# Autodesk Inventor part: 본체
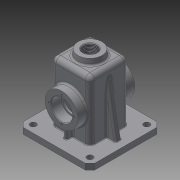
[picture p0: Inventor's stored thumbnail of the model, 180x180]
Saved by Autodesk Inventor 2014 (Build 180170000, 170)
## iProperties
Created: 2017-08
Part Number: 본체
Material: 일반
Document SubType Name: Modeling
Designer: user
Density: 1 g/cm^3
Appearance: 기본값
Author: user
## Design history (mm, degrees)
sketch "스케치1"
  geometry: L1 (32.5, -32.5)-(-32.5, -32.5); L2 (-32.5, -32.5)-(-32.5, 32.5); L3 (-32.5, 32.5)-(32.5, 32.5); L4 (32.5, 32.5)-(32.5, -32.5); L5 (32.5, -32.5)-(-32.5, 32.5); L6 (-32.5, -32.5)-(32.5, 32.5); 1 further point
  constraints: 12 end point, 2 midpoint, 2 parallel, 2 perpendicular, 1 horizontal
  dimensions: "d0" = 65 distance of L2.end L3.end
extrude "돌출1" new body sketch "스케치1" distance "d1" = 55; taper "d3" = 0 deg; dims "d2" = 55, "d4" = 0
fillet "모깎기1" dims "d5" = 8
fillet "모깎기2" dims "d6" = 8
feature "쉘1" dims "d7" = 5
sketch "스케치2"
  geometry: L1 (24.5, 32.5)-(-24.5, 32.5) reference; L2 (-32.5, 24.5)-(-32.5, -24.5) reference; L3 (-24.5, -32.5)-(24.5, -32.5) reference; L4 (32.5, -24.5)-(32.5, 24.5) reference; L5 (-60, -60)-(60, -60); L6 (60, -60)-(60, 60); L7 (60, 60)-(-60, 60); L8 (-60, 60)-(-60, -60); L9 (-60, -60)-(60, 60); L10 (60, -60)-(-60, 60); A1 r 8 centre (24.5, 24.5) between (32.5, 24.5) and (24.5, 32.5) reference; A2 r 8 centre (-24.5, 24.5) between (-24.5, 32.5) and (-32.5, 24.5) reference; A3 r 8 centre (-24.5, -24.5) between (-32.5, -24.5) and (-24.5, -32.5) reference; A4 r 8 centre (24.5, -24.5) between (24.5, -32.5) and (32.5, -24.5) reference; 1 further point
  constraints: 12 end point, 2 midpoint, 2 parallel, 2 perpendicular, 1 horizontal
  dimensions: "d8" = 120 distance of L6.end L7.end
extrude "돌출2" join sketch "스케치2" distance "d9" = 10; taper "d10" = 0 deg
sketch "스케치3"
  geometry: C1 r 27.5 at (24.5, -47); 1 further point
  constraints: 1 centre point, 1 coincident
  dimensions: "d11" = 55 diameter of C1
extrude "돌출3" join sketch "스케치3" distance "d12" = 15; taper "d13" = 0 deg
sketch "스케치4"
  geometry: C1 r 27.5 at (0, 0) reference; A1 r 21 centre (0, 0) between (0, 21) and (-21, 0); 2 further points
  constraints: 4 point on circle, 2 horizontal alignment, 2 vertical alignment, 1 centre point, 1 coincident
  dimensions: "d14" = 42 diameter of A1
hole "구멍1" sketch "스케치4" at (0, 21), (-21, 0), (0, -21), (21, 0) diameter "d15" = 3.242; stored, may be unused: countersink angle "d19" = 90 deg, drill point angle "d21" = 118 deg; dims "d16" = 8, "d17" = 4, "d18" = 2, "d20" = 10
sketch "스케치6"
  geometry: L1 (-24.5, -32.5)-(24.5, -32.5) reference; L2 (3, -42.5)-(-3, -42.5); L3 (-3, -42.5)-(-3, -32.5); L4 (-3, -32.5)-(3, -32.5); L5 (3, -32.5)-(3, -42.5); L6 (3, -42.5)-(-3, -32.5); L7 (-3, -42.5)-(3, -32.5); 4 further points
  constraints: 12 end point, 4 midpoint, 2 parallel, 2 vertical alignment, 1 horizontal, 1 perpendicular, 1 point on line
  dimensions: "d25" = 6 distance between parallel lines of L5 L3; "d26" = 10 distance of L4.end L2.start
extrude "돌출5" join sketch "스케치6" stored distance "d27" = 15; taper "d28" = 0 deg
node "작업 평면1"
sketch "스케치8"
  geometry: C1 r 20 at (0, 0); 1 further point
  constraints: 1 centre point, 1 coincident
  dimensions: "d30" = 40 diameter of C1
extrude "돌출6" join sketch "스케치8" stored distance "d31" = 15; taper "d32" = 7 deg
hole "구멍2" diameter "d35" = 22.835; stored, may be unused: countersink angle "d39" = 90 deg, drill point angle "d41" = 118 deg; dims "d33" = 10, "d34" = 10, "d36" = 8, "d37" = 4, "d38" = 2, "d40" = 10
sketch "스케치10"
  geometry: L1 (-32.5, -45)-(-32.5, 47) reference; L2 (60, -45)-(-60, -45) reference; L3 (32.5, 47)-(32.5, -45) reference; L4 (-32.5, 42.905)-(-48, -45); L5 (-60, -55)-(-60, -45) reference; 1 further point
  constraints: 2 end point, 2 point on line
  dimensions: "d42" = 10 deg angle of L5 L4; "d43" = 12 distance of L4.end L2.end
feature "리브1" sketch "스케치10" dims "d44" = 1, "d45" = 10, "d46" = 0, "d47" = 0, "d48" = 1, "d49" = 1
hole "구멍3" diameter "d52" = 30; stored, may be unused: countersink angle "d56" = 90 deg, drill point angle "d58" = 118 deg; dims "d50" = 10, "d51" = 10, "d53" = 8, "d54" = 35, "d55" = 17, "d57" = 10
fillet "모깎기3" dims "d59" = 0.3
chamfer "모따기1" distance "d60" = 8; stored, may be unused: second distance "d61" = 2, angle "d62" = 45 deg
sketch "스케치11"
  geometry: L1 (-60, 52)-(-60, -52) reference; L2 (52, 60)-(-52, 60) reference; 5 further points
  constraints: 2 horizontal alignment, 2 vertical alignment
  dimensions: "d63" = 95 distance of point (47.5, 47.5) point (-47.5, 47.5); "d64" = 95 distance of point (47.5, -47.5) point (47.5, 47.5); "d65" = 12.5 distance from line of point (-47.5, 47.5) L1; "d66" = 12.5 distance from line of L2 point (-47.5, 47.5)
hole "구멍4" sketch "스케치11" at (-47.5, 47.5), (47.5, 47.5), (47.5, -47.5), (-47.5, -47.5) diameter "d67" = 10; stored, may be unused: countersink angle "d71" = 90 deg, drill point angle "d73" = 118 deg; dims "d68" = 8, "d69" = 35, "d70" = 17, "d72" = 10
fillet "모깎기4" dims "d74" = 3
fillet "모깎기5" dims "d75" = 3
fillet "모깎기6" dims "d76" = 3
fillet "모깎기7" dims "d77" = 3
fillet "모깎기8" dims "d78" = 3
fillet "모깎기9" dims "d79" = 3
fillet "모깎기10" dims "d80" = 3
fillet "모깎기11" dims "d81" = 3
fillet "모깎기12" dims "d82" = 3
fillet "모깎기13" dims "d83" = 3
fillet "모깎기14" dims "d84" = 1
chamfer "모따기2" distance "d85" = 1; stored, may be unused: second distance "d86" = 2, angle "d87" = 45 deg
sketch "스케치12"
  geometry: L1 (57, 0)-(57, 91) reference; L2 (44.5, -18)-(4.5, -18) reference; 1 further point
  constraints: 1 other
  dimensions: "d88" = 32.5 distance from line of point (24.5, 8) L1; "d89" = 26 distance from line of point (24.5, 8) L2
feature "엠보싱1" sketch "스케치12" dims "d90" = 0.5, "d91" = 0
node "솔리드1"
mirror "대칭1"
mirror "대칭2"
mirror "대칭3"
other parameters: "d29" = 65
